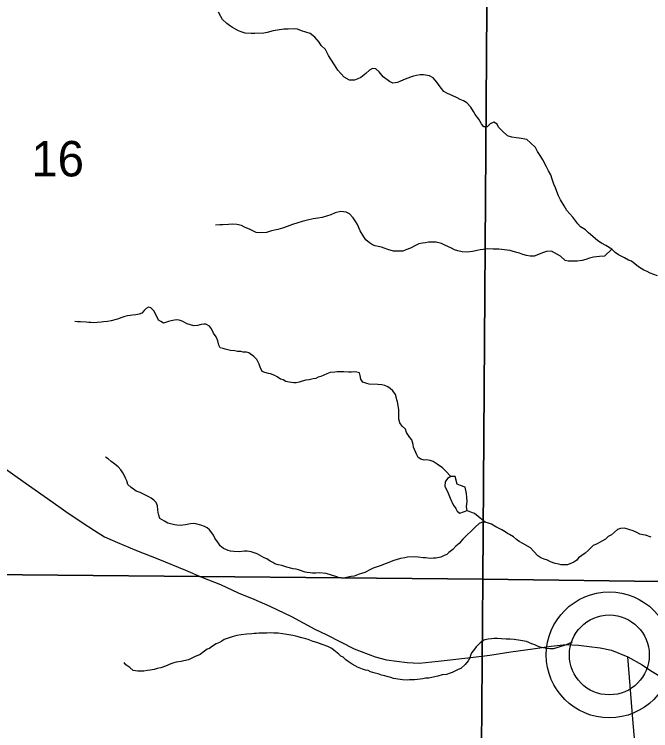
# Model space of a CAD drawing. Extents: x 0 to 34, y 0 to 22.
# Drawn here: x 4.616 to 5.367, y 17.947 to 18.793 of the extents above; entities that cross this region are included whole.
import ezdxf

# ---------------------------------------------------------------- set-up
doc = ezdxf.new("R2010")
doc.units = 0
for name, color, linetype in [('GM_X_Corporation', 7, 'Continuous'), ('GM_X_County_Road', 7, 'Continuous'), ('GM_X_Minor_River', 7, 'Continuous'), ('GM_X_Section_Text', 7, 'Continuous'), ('GM_X_State_Route', 7, 'Continuous'), ('GM_X_Unincorporated', 7, 'Continuous'), ('GM_X_Unincorporated_Location', 7, 'Continuous')]:
    doc.layers.add(name, color=color, linetype=linetype)

msp = doc.modelspace()

# ---------------------------------------------------------------- linework, layer by layer
at = {"layer": 'GM_X_Corporation'}
for points in [[(4.16543, 19.14124), (5.17593, 19.13773), (5.16898, 18.12578), (4.16466, 18.13521)], [(4.16466, 18.13521), (5.16898, 18.12578), (5.16095, 17.13356), (4.16029, 17.13684)]]:
    msp.add_lwpolyline(points, close=True, dxfattribs=at)
for points in [[(5.64648, 18.1197), (5.16898, 18.12578), (5.17593, 19.13773)], [(5.16095, 17.13356), (5.16898, 18.12578), (5.64648, 18.1197), (5.64048, 18.05165), (5.64113, 18.02891), (5.64083, 17.99748), (5.63652, 17.97333), (5.63077, 17.95224), (5.62493, 17.90957)]]:
    msp.add_lwpolyline(points, dxfattribs=at)
at = {"layer": 'GM_X_County_Road'}
msp.add_lwpolyline([(5.08824, 17.25806), (5.184, 17.35078), (5.22472, 17.39151), (5.24033, 17.40267), (5.26545, 17.41401), (5.29501, 17.42419), (5.30683, 17.43158), (5.31422, 17.44143), (5.32292, 17.47214), (5.33524, 17.52419), (5.34181, 17.55228), (5.34395, 17.58003), (5.34953, 17.63012), (5.35528, 17.67873), (5.36086, 17.72421), (5.36201, 17.76839), (5.35873, 17.81027), (5.35429, 17.85904), (5.35248, 17.88515), (5.34641, 17.95576), (5.34012, 18.03432)], dxfattribs=at)
at = {"layer": 'GM_X_Minor_River'}
for points in [[(4.98939, 18.74029), (4.9864, 18.74449), (4.98305, 18.75135), (4.97779, 18.75633), (4.97555, 18.76014), (4.9703, 18.76626), (4.96503, 18.77048), (4.95485, 18.77361), (4.94995, 18.77555), (4.94654, 18.77596), (4.93898, 18.77565), (4.93368, 18.7757), (4.92119, 18.77354), (4.91399, 18.77171), (4.9102, 18.77099), (4.89961, 18.77033), (4.89507, 18.77037), (4.88827, 18.77081), (4.88449, 18.77199), (4.88035, 18.77354), (4.87658, 18.77547), (4.87319, 18.7774), (4.8698, 18.77971), (4.86642, 18.7824), (4.86154, 18.78699), (4.85929, 18.79043), (4.85668, 18.79576)], [(5.37514, 18.4841), (5.36647, 18.48721), (5.3627, 18.48915), (5.35893, 18.49108), (5.35253, 18.49493), (5.34426, 18.50145), (5.34087, 18.50262), (5.33597, 18.50532), (5.32919, 18.5088), (5.32505, 18.51187), (5.3213, 18.5157), (5.31414, 18.51994), (5.30887, 18.52264), (5.30473, 18.52534), (5.29872, 18.5307), (5.29345, 18.53492), (5.29008, 18.53837), (5.28405, 18.54222), (5.28105, 18.54566), (5.27506, 18.55368), (5.26793, 18.56133), (5.26495, 18.56705), (5.26046, 18.57392), (5.25823, 18.57887), (5.25637, 18.58381), (5.25451, 18.588), (5.25266, 18.59257), (5.25081, 18.59828), (5.24895, 18.6036), (5.24634, 18.60818), (5.2441, 18.61275), (5.23963, 18.62114), (5.23739, 18.62495), (5.23327, 18.63106), (5.23104, 18.63563), (5.22503, 18.64138), (5.22089, 18.6452), (5.21183, 18.64681), (5.20805, 18.64722), (5.20314, 18.64803), (5.19786, 18.64959), (5.19147, 18.65534), (5.18735, 18.65993), (5.18586, 18.66336), (5.18172, 18.66567), (5.17754, 18.66381), (5.17373, 18.66006), (5.16995, 18.6601), (5.16733, 18.66391), (5.16397, 18.66925), (5.15985, 18.6746), (5.15761, 18.67841), (5.15462, 18.68337), (5.14974, 18.68835), (5.14597, 18.69104), (5.1422, 18.69259), (5.13844, 18.69452), (5.13278, 18.69723), (5.12713, 18.69956), (5.12261, 18.70188), (5.11849, 18.7076), (5.11437, 18.71295), (5.11024, 18.71792), (5.10572, 18.72024), (5.09893, 18.72144), (5.09477, 18.72148), (5.0906, 18.72076), (5.08681, 18.72004), (5.0834, 18.71893), (5.07695, 18.71633), (5.07164, 18.71411), (5.06823, 18.71262), (5.06255, 18.71192), (5.05841, 18.71385), (5.05126, 18.71923), (5.04638, 18.72496), (5.04263, 18.72879), (5.03848, 18.72921), (5.03506, 18.72697), (5.03049, 18.72322), (5.02478, 18.71834), (5.02137, 18.71685), (5.0172, 18.71538), (5.01153, 18.71543), (5.00512, 18.7189), (5.00099, 18.72311), (4.99762, 18.72731), (4.9935, 18.73342), (4.98939, 18.74029)], [(5.3213, 18.5157), (5.31254, 18.50744), (5.30649, 18.50712), (5.29967, 18.50642), (5.29475, 18.50495), (5.29058, 18.50347), (5.28603, 18.50238), (5.28035, 18.50167), (5.27695, 18.50132), (5.26938, 18.50139), (5.26599, 18.50218), (5.26035, 18.50754), (5.25357, 18.5114), (5.24981, 18.51333), (5.24413, 18.513), (5.2392, 18.51116), (5.23276, 18.50856), (5.22934, 18.50745), (5.22481, 18.5075), (5.22027, 18.5083), (5.21612, 18.50947), (5.21197, 18.51103), (5.2048, 18.51299), (5.20103, 18.51417), (5.19763, 18.51458), (5.19121, 18.51539), (5.18781, 18.51581), (5.1844, 18.51584), (5.181, 18.51587), (5.17419, 18.51593), (5.16927, 18.51522), (5.16549, 18.51488), (5.16208, 18.51415), (5.15678, 18.51306), (5.15034, 18.51198), (5.14429, 18.51242), (5.13938, 18.5136), (5.13523, 18.51478), (5.13185, 18.51671), (5.12393, 18.52057), (5.12016, 18.5225), (5.11375, 18.52408), (5.10996, 18.52412), (5.10467, 18.52379), (5.10126, 18.52306), (5.09747, 18.52271), (5.09331, 18.522), (5.08838, 18.51977), (5.08344, 18.51678), (5.07775, 18.51493), (5.07434, 18.51345), (5.06715, 18.51314), (5.06337, 18.51317), (5.05658, 18.51513), (5.05243, 18.51669), (5.04903, 18.51786), (5.04526, 18.51903), (5.04186, 18.51982), (5.03846, 18.52061), (5.03508, 18.5233), (5.03057, 18.52675), (5.02832, 18.53019), (5.02384, 18.53743), (5.02087, 18.54467), (5.019, 18.5481), (5.01563, 18.55268), (5.0115, 18.55727), (5.00736, 18.55958), (5.00131, 18.56002), (4.9945, 18.55857), (4.98919, 18.55634), (4.98426, 18.55449), (4.97895, 18.55302), (4.97403, 18.55231), (4.96835, 18.5516), (4.96191, 18.54977), (4.95547, 18.54831), (4.95054, 18.54684), (4.9441, 18.545), (4.93765, 18.54241), (4.93235, 18.54056), (4.92666, 18.5391), (4.91946, 18.53727), (4.9134, 18.53543), (4.9047, 18.53513), (4.9013, 18.53554), (4.89414, 18.53902), (4.88735, 18.54174), (4.88396, 18.54367), (4.8783, 18.54486), (4.87338, 18.54528), (4.86847, 18.54495), (4.86165, 18.54425), (4.85825, 18.54428), (4.85333, 18.54395)], [(4.85574, 18.40739), (4.85388, 18.41196), (4.85089, 18.41654), (4.84828, 18.4215), (4.84603, 18.42493), (4.84189, 18.42724), (4.83924, 18.42727), (4.83621, 18.42654), (4.83204, 18.42544), (4.8275, 18.4251), (4.81958, 18.42745), (4.81393, 18.43054), (4.81016, 18.43171), (4.80751, 18.43212), (4.80486, 18.43176), (4.8007, 18.43104), (4.79767, 18.43031), (4.7916, 18.42847), (4.78859, 18.4304), (4.78595, 18.43194), (4.78409, 18.43537), (4.7826, 18.43803), (4.78074, 18.4426), (4.77698, 18.44643), (4.77396, 18.44722), (4.77131, 18.44573), (4.76902, 18.44309), (4.76597, 18.44009), (4.76294, 18.43898), (4.75915, 18.43825), (4.75499, 18.43791), (4.75234, 18.43718), (4.74931, 18.43683), (4.74628, 18.4361), (4.74135, 18.43463), (4.7387, 18.43351), (4.73604, 18.43278), (4.72998, 18.43094), (4.72581, 18.43022), (4.72089, 18.42989), (4.71824, 18.42953), (4.71333, 18.4292), (4.70878, 18.42886), (4.70614, 18.42888), (4.70349, 18.42891), (4.70047, 18.42932), (4.69367, 18.42976), (4.69026, 18.42979), (4.68724, 18.4302)], [(5.13115, 18.24703), (5.12463, 18.25395), (5.12125, 18.25739), (5.11485, 18.26163), (5.11034, 18.26508), (5.10657, 18.26625), (5.10241, 18.26667), (5.09938, 18.26632), (5.09561, 18.26749), (5.0926, 18.26942), (5.09073, 18.27285), (5.08702, 18.28198), (5.08666, 18.28502), (5.08481, 18.29035), (5.08256, 18.2934), (5.07882, 18.29913), (5.07734, 18.30293), (5.07358, 18.30676), (5.07096, 18.31058), (5.06948, 18.31476), (5.06956, 18.32614), (5.06812, 18.33526), (5.06738, 18.33792), (5.06665, 18.34134), (5.06554, 18.344), (5.06254, 18.3482), (5.05954, 18.35126), (5.05653, 18.35319), (5.05313, 18.35474), (5.04974, 18.35553), (5.04482, 18.35595), (5.03461, 18.35605), (5.03197, 18.35683), (5.02707, 18.35877), (5.02483, 18.36221), (5.0241, 18.36638), (5.02299, 18.36943), (5.01997, 18.3706), (5.01619, 18.37063), (5.01354, 18.37028), (5.01014, 18.37031), (5.00485, 18.37074), (4.99691, 18.37081), (4.99388, 18.37046), (4.98858, 18.37013), (4.98479, 18.36827), (4.98099, 18.36679), (4.97758, 18.3653), (4.97455, 18.36457), (4.97151, 18.36308), (4.96848, 18.36235), (4.96356, 18.36126), (4.95977, 18.36092), (4.95561, 18.35982), (4.95182, 18.35871), (4.94841, 18.35799), (4.94576, 18.35763), (4.94009, 18.35844), (4.93631, 18.35924), (4.93292, 18.36117), (4.92991, 18.36233), (4.92577, 18.36503), (4.92313, 18.36657), (4.91823, 18.36851), (4.91559, 18.36891), (4.91143, 18.37009), (4.90842, 18.37125), (4.90581, 18.37621), (4.9047, 18.38001), (4.90209, 18.38535), (4.89833, 18.38879), (4.89232, 18.3934), (4.88967, 18.39418), (4.88589, 18.39422), (4.88325, 18.39462), (4.87909, 18.39466), (4.87607, 18.39545), (4.87078, 18.39588), (4.86474, 18.39745), (4.8621, 18.39823), (4.8587, 18.39902), (4.85721, 18.40245), (4.85574, 18.40739)], [(4.79706, 18.19214), (4.79292, 18.19446), (4.79028, 18.196), (4.78727, 18.19754), (4.78616, 18.20135), (4.78543, 18.20477), (4.78507, 18.2078), (4.78473, 18.21236), (4.78325, 18.21654), (4.78024, 18.21923), (4.77723, 18.22153), (4.7746, 18.22307), (4.77196, 18.22423), (4.76819, 18.22617), (4.76404, 18.2281), (4.75952, 18.22966), (4.75651, 18.23234), (4.7535, 18.23427), (4.74974, 18.23771), (4.74864, 18.24189), (4.74678, 18.24533), (4.74566, 18.24799), (4.74379, 18.25142), (4.74155, 18.25486), (4.73817, 18.25868), (4.73253, 18.2629), (4.7299, 18.26482), (4.72652, 18.26789), (4.72313, 18.26982)], [(5.15048, 18.20682), (5.14939, 18.21132), (5.15028, 18.21814), (5.14999, 18.22233), (5.14933, 18.22728), (5.14796, 18.23453), (5.14231, 18.23655), (5.13855, 18.23814), (5.13608, 18.24731), (5.13115, 18.24703), (5.12693, 18.24483), (5.12419, 18.2407), (5.12409, 18.23576), (5.12771, 18.22733)], [(5.12771, 18.22733), (5.13025, 18.22158), (5.13388, 18.21352), (5.13683, 18.20928), (5.13866, 18.2062), (5.14165, 18.20387), (5.15048, 18.20682)], [(5.17145, 18.19321), (5.16582, 18.19782), (5.16319, 18.20012), (5.15905, 18.20357), (5.15452, 18.20513), (5.15075, 18.20668), (5.15048, 18.20682)], [(5.23733, 18.15126), (5.23356, 18.15357), (5.22906, 18.15855), (5.22493, 18.16276), (5.21589, 18.16815), (5.21175, 18.17046), (5.20837, 18.17277), (5.20498, 18.17584), (5.20047, 18.17853), (5.19783, 18.17969), (5.19519, 18.18162), (5.19143, 18.18431), (5.18427, 18.18778), (5.179, 18.19087), (5.17561, 18.19204), (5.17145, 18.19321), (5.16729, 18.19287), (5.16464, 18.19176), (5.15969, 18.18725), (5.14521, 18.17298), (5.14102, 18.16809), (5.13683, 18.16471), (5.1334, 18.16095), (5.12884, 18.15758), (5.12617, 18.15495), (5.12314, 18.15384), (5.11935, 18.15198), (5.11329, 18.1509), (5.11064, 18.15055), (5.10647, 18.1502), (5.10119, 18.15101), (5.09816, 18.15104), (5.09249, 18.15185), (5.08834, 18.15227), (5.08002, 18.15197), (5.07661, 18.15124), (5.07168, 18.15015), (5.06372, 18.14795), (5.05462, 18.14424), (5.05159, 18.14313), (5.04893, 18.14202), (5.03946, 18.13907), (5.0368, 18.13758), (5.02959, 18.13385), (5.02542, 18.13275), (5.02276, 18.13164), (5.0167, 18.12942), (5.01329, 18.12907), (5.0042, 18.12726), (4.99928, 18.12731), (4.99627, 18.12847), (4.98382, 18.13276), (4.9755, 18.13322), (4.97172, 18.13288), (4.96756, 18.13291), (4.96492, 18.13332), (4.96152, 18.13373), (4.95887, 18.13413), (4.95133, 18.13686), (4.94831, 18.13764), (4.94491, 18.13806), (4.93736, 18.14002), (4.93132, 18.14197), (4.92717, 18.14277), (4.92339, 18.14394), (4.92076, 18.14549), (4.91774, 18.14703), (4.91361, 18.1501), (4.91059, 18.15127), (4.90795, 18.15281), (4.90494, 18.15435), (4.90231, 18.15589), (4.89891, 18.15706), (4.89514, 18.15824), (4.8906, 18.15904), (4.88758, 18.15906), (4.88417, 18.15872), (4.88152, 18.15836), (4.87472, 18.15843), (4.87094, 18.15884), (4.8683, 18.15963), (4.86528, 18.16079), (4.86264, 18.16195), (4.85851, 18.1654), (4.85664, 18.16845), (4.85252, 18.17418), (4.85066, 18.17799), (4.84878, 18.18066), (4.84616, 18.1841), (4.84315, 18.18641), (4.84014, 18.18795), (4.83599, 18.18951), (4.82995, 18.19108), (4.82693, 18.19149), (4.82353, 18.19114), (4.81784, 18.19005), (4.81444, 18.1897), (4.81179, 18.18935), (4.80763, 18.18977), (4.80461, 18.19018), (4.79706, 18.19214)], [(5.36759, 18.17546), (5.3608, 18.1778), (5.35816, 18.1782), (5.35438, 18.179), (5.35062, 18.18093), (5.34647, 18.18286), (5.3359, 18.18599), (5.33136, 18.18566), (5.32795, 18.18455), (5.32072, 18.17817), (5.31692, 18.17631), (5.3135, 18.17331), (5.30666, 18.1692), (5.304, 18.16771), (5.29907, 18.16548), (5.29336, 18.15985), (5.28955, 18.15647), (5.28195, 18.15123), (5.27966, 18.14821), (5.27624, 18.14597), (5.27358, 18.14486), (5.26865, 18.14301), (5.266, 18.14265), (5.26147, 18.1427), (5.25845, 18.14348), (5.25429, 18.14428), (5.24863, 18.14623), (5.24524, 18.14816), (5.2411, 18.14971), (5.23733, 18.15126)], [(5.27441, 18.05156), (5.2672, 18.04821), (5.25849, 18.04564), (5.25205, 18.0438), (5.24788, 18.04346), (5.24448, 18.04387), (5.23995, 18.04467), (5.23655, 18.04546), (5.23316, 18.04663), (5.23014, 18.04818), (5.22675, 18.04972), (5.22034, 18.05244), (5.21317, 18.05364), (5.20561, 18.05447), (5.20107, 18.05489), (5.19654, 18.05494), (5.19087, 18.05537), (5.18595, 18.05579), (5.18217, 18.05583), (5.17914, 18.05548), (5.17498, 18.05514), (5.1712, 18.05441), (5.16816, 18.05292), (5.1655, 18.05067), (5.16092, 18.04617), (5.15787, 18.04164), (5.15558, 18.03901), (5.15442, 18.03561), (5.15327, 18.03296), (5.15135, 18.02957), (5.14791, 18.02505), (5.14296, 18.02054), (5.13955, 18.01906), (5.13272, 18.01571), (5.13007, 18.01498), (5.1259, 18.0135), (5.1206, 18.01279), (5.11567, 18.01132), (5.10999, 18.01023), (5.10506, 18.00914), (5.10128, 18.0088), (5.09787, 18.00807), (5.09181, 18.00737), (5.08803, 18.00702), (5.08236, 18.00707), (5.07971, 18.00672), (5.07404, 18.00715), (5.07102, 18.00756), (5.06346, 18.00877), (5.06007, 18.00994), (5.05705, 18.01072), (5.0529, 18.0119), (5.04912, 18.01269), (5.04535, 18.01424), (5.04157, 18.01504), (5.03629, 18.0166), (5.03328, 18.01815), (5.03025, 18.01856), (5.02686, 18.01973), (5.02083, 18.02206), (5.01819, 18.0236), (5.01442, 18.02553), (5.00991, 18.02861), (5.0069, 18.03053), (5.00389, 18.03359), (5.00126, 18.03513), (4.99863, 18.03743), (4.99299, 18.04204), (4.99035, 18.04396), (4.98583, 18.04628), (4.97904, 18.04861), (4.97263, 18.05095), (4.96848, 18.05213), (4.96245, 18.05446), (4.95981, 18.05524), (4.9549, 18.0568), (4.94811, 18.05876), (4.94433, 18.05956), (4.93753, 18.06038), (4.92695, 18.06199), (4.92204, 18.06204), (4.91788, 18.06246), (4.91372, 18.06212), (4.90918, 18.06216), (4.90427, 18.0622), (4.90162, 18.06185), (4.89897, 18.06187), (4.89594, 18.06152), (4.89026, 18.06082), (4.88345, 18.06012), (4.87853, 18.05941), (4.8755, 18.05868), (4.87285, 18.05794), (4.86678, 18.05572), (4.86337, 18.05462), (4.86071, 18.05275), (4.85805, 18.05126), (4.85388, 18.0494), (4.84856, 18.04603), (4.8459, 18.04416), (4.84324, 18.04305)], [(4.84324, 18.04305), (4.8402, 18.0408), (4.83488, 18.03706), (4.82843, 18.03409), (4.82501, 18.0326), (4.82122, 18.03074), (4.81591, 18.02927), (4.8125, 18.02854), (4.80682, 18.02784), (4.80379, 18.02711), (4.80038, 18.026), (4.79393, 18.02303), (4.78862, 18.02118), (4.78446, 18.02046), (4.78067, 18.01936), (4.77612, 18.01826), (4.77272, 18.01792), (4.76855, 18.0172), (4.76137, 18.01726), (4.75608, 18.01807), (4.75194, 18.02152), (4.74743, 18.0246), (4.74518, 18.02765)]]:
    msp.add_lwpolyline(points, dxfattribs=at)
at = {"layer": 'GM_X_State_Route'}
for points in [[(4.5682, 18.28215), (4.62855, 18.23971), (4.65873, 18.21849), (4.67645, 18.20583), (4.69572, 18.19298), (4.71012, 18.18325), (4.7222, 18.17605), (4.73758, 18.16923), (4.75977, 18.15969), (4.78488, 18.14976), (4.81778, 18.13652), (4.83783, 18.12796), (4.85886, 18.11978), (4.88008, 18.10985), (4.89858, 18.10245), (4.91726, 18.09408), (4.94296, 18.08162), (4.97061, 18.06702), (4.98463, 18.06001), (5.01694, 18.04347), (5.04186, 18.03432), (5.05491, 18.03081), (5.07963, 18.0275), (5.09345, 18.02653), (5.11624, 18.02916), (5.15455, 18.03344), (5.17696, 18.03613), (5.2017, 18.03996), (5.22779, 18.04347), (5.24939, 18.04658), (5.26711, 18.04872), (5.28171, 18.04795), (5.29432, 18.0465), (5.30741, 18.04483), (5.32065, 18.04211), (5.34012, 18.03432)], [(5.34012, 18.03432), (5.35706, 18.02458), (5.36659, 18.01816), (5.37263, 18.01465), (5.38275, 18.00784), (5.39632, 17.99927), (5.40545, 17.99258), (5.41272, 17.98744)]]:
    msp.add_lwpolyline(points, dxfattribs=at)
at = {"layer": 'GM_X_Unincorporated'}
for radius in [0.0744, 0.04716]:
    msp.add_circle((5.31813, 18.03643), radius, dxfattribs=at)
at = {"layer": 'GM_X_Unincorporated_Location'}
msp.add_line((5.31813, 18.03643), (5.31813, 18.03643), dxfattribs=at)

# ---------------------------------------------------------------- texts
at = {"layer": 'GM_X_Section_Text'}
msp.add_text('16', height=0.041856, rotation=0.00001, dxfattribs=at).set_placement((4.63563, 18.60161))

doc.saveas('drawing.dxf')
